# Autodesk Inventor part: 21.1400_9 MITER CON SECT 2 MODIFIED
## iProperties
Created: 2006-12
Part Number: 21.1400_9 MITER CON SECT 2 MODIFIED
Document SubType Name: Modeling
Designer: Andy Moles
Material: Alloy Steel
Density: 7.85 g/cm^3
Mass: 20.5328 g
Surface Area: 16.2437 cm^2
Volume: 2.61565 cm^3
Author: Andy Moles
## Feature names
1. Extrusion1
2. Revolution1
3. Extrusion2
4. Extrusion3
5. Chamfer1
6. Hole2
7. Chamfer2
8. Hole3
